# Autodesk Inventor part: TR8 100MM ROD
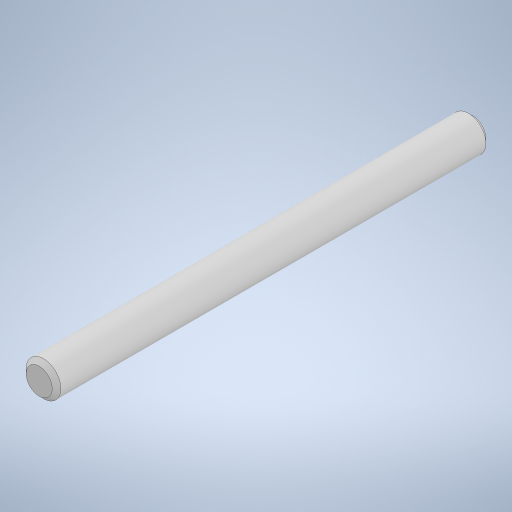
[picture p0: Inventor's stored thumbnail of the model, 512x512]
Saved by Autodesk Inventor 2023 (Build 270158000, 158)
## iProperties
Created: 2025-07
Part Number: TR8 100MM ROD
Material: Generic
Document SubType Name: Modeling
Designer: erjon
Density: 1 g/cm^3
Appearance: Default
Author: erjon
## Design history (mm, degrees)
feature "Base1"
body "Solid1"
